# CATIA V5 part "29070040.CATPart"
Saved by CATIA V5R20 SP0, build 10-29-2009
Part number: 29070040
Definition: NONE
Nomenclature: 29070040
Source: Unknown
Description: 29070040
Bounding box of the stored display mesh (mm): x -20 to 44.548, y -49 to 83.548, z -39 to 39
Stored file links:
  C:\Users\Utente\Desktop\IO LAVORO\3D X SITO CF\X SITO\PLASTICA\RF1\29070040.CATPart
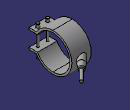
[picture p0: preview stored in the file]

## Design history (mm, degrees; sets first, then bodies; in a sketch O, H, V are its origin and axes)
Body1 "29070040" (main body)
  Solid1: solid without history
